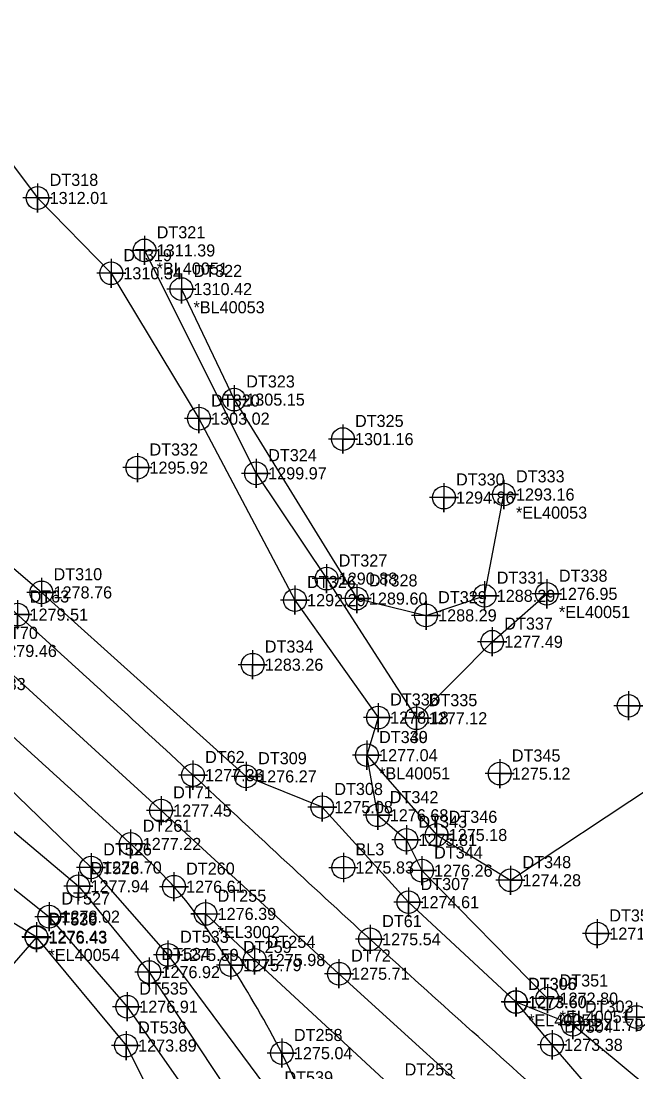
# Model space of a CAD drawing. Extents: x 1391270 to 1392151, y 960049 to 960667.
# Drawn here: x 1391417.5 to 1391544.4, y 960444.8 to 960661.8 of the extents above; entities that cross this region are included whole.
import ezdxf

# ---------------------------------------------------------------- set-up
doc = ezdxf.new("R2010")
doc.units = 0
for name, color, linetype in [('Cogo Default Point CELL', 7, 'Continuous'), ('COGO Default Point Elevation', 7, 'Continuous'), ('COGO Default Point Number', 7, 'Continuous'), ('Exist DTM Breakline', 7, 'Continuous'), ('Exist DTM Breakline Cogo Comment', 7, 'Continuous'), ('Exist DTM Breakline Cogo Elevation', 7, 'Continuous'), ('Exist DTM Breakline Cogo Number', 7, 'Continuous'), ('Exist DTM Breakline Cogo Point CELL', 7, 'Continuous'), ('Exist DTM Crownline', 7, 'Continuous'), ('Exist DTM Crownline Cogo Elevation', 7, 'Continuous'), ('Exist DTM Crownline Cogo Number', 7, 'Continuous'), ('Exist DTM Crownline Cogo Point CELL', 7, 'Continuous'), ('Exist DTM Regular Point CELL', 7, 'Continuous'), ('Exist DTM Regular Point Cogo Elevation', 7, 'Continuous'), ('Exist DTM Regular Point Cogo Number', 7, 'Continuous'), ('Exist Roads EOP', 7, 'Continuous'), ('Exist Roads EOP Cogo Elevation', 7, 'Continuous'), ('Exist Roads EOP Cogo Number', 7, 'Continuous'), ('Exist Roads EOP Cogo Point CELL', 7, 'Continuous'), ('Exist Roads EOT', 7, 'Continuous'), ('Exist Roads EOT Cogo Comment', 7, 'Continuous'), ('Exist Roads EOT Cogo Elevation', 7, 'Continuous'), ('Exist Roads EOT Cogo Number', 7, 'Continuous'), ('Exist Roads EOT Cogo Point CELL', 7, 'Continuous')]:
    doc.layers.add(name, color=color, linetype=linetype)

msp = doc.modelspace()

# ---------------------------------------------------------------- linework, layer by layer
at = {"layer": 'Cogo Default Point CELL'}
for points in [[(1391484.045, 960490.035), (1391484.045, 960487.035)], [(1391481.045, 960487.035), (1391484.045, 960487.035)], [(1391484.045, 960487.035), (1391487.045, 960487.035)], [(1391484.045, 960487.035), (1391484.045, 960484.035)]]:
    msp.add_lwpolyline(points, dxfattribs=at)
msp.add_circle((1391484.045, 960487.035), 2.344, dxfattribs=at)
at = {"layer": 'Exist DTM Breakline'}
for points in [[(1391393.449, 960661.814), (1391420.927, 960625.274), (1391436.139, 960609.727), (1391454.255, 960579.709), (1391474.064, 960542.237), (1391491.205, 960517.974), (1391488.925, 960510.22), (1391503.285, 960493.748), (1391518.522, 960484.392), (1391548.09, 960503.995), (1391563.385, 960512.482)], [(1391443.022, 960614.446), (1391466.033, 960568.417), (1391480.588, 960546.677), (1391499.161, 960517.839), (1391514.762, 960533.642), (1391526.037, 960543.54)], [(1391572.148, 960404.532), (1391566.45, 960414.023), (1391560.493, 960420.45), (1391551.134, 960422.515), (1391527.127, 960450.418), (1391519.65, 960459.266), (1391497.478, 960479.87), (1391479.684, 960499.497), (1391463.962, 960505.846), (1391421.736, 960543.837), (1391384.984, 960575.223), (1391359.376, 960600.331), (1391347.861, 960610.635)], [(1391450.622, 960606.46), (1391461.505, 960583.645), (1391486.818, 960542.56), (1391501.108, 960539.09), (1391513.198, 960543.133), (1391517.176, 960564.054)], [(1391324.233, 960586.705), (1391339.042, 960571.952), (1391361.254, 960553.328), (1391397.359, 960520.55), (1391431.984, 960487.022), (1391447.858, 960468.977), (1391469.387, 960439.951), (1391481.042, 960400.574)], [(1391316.128, 960578.463), (1391335.373, 960567.825), (1391355.688, 960547.259), (1391385.482, 960507.01), (1391423.359, 960476.875), (1391439.432, 960458.285), (1391460.969, 960427.473), (1391472.339, 960397.865), (1391475.509, 960385.212), (1391483.88, 960383.187), (1391486.523, 960363.38), (1391492.773, 960311.276)], [(1391303.798, 960568.714), (1391337.195, 960549.348), (1391355.915, 960524.922), (1391369.834, 960491.808), (1391382.04, 960457.756), (1391381.24, 960442.404), (1391402.896, 960452.148), (1391420.738, 960472.565), (1391439.191, 960450.264), (1391454.114, 960420.78), (1391463.153, 960401.998), (1391468.38, 960380.734), (1391451.764, 960376.78), (1391432.731, 960383.561)], [(1391374.906, 960532.045), (1391391.307, 960515.216), (1391429.365, 960483.152), (1391444, 960465.435), (1391465.005, 960433.545)], [(1391491.131, 960497.813), (1391488.925, 960510.22)], [(1391491.131, 960497.813), (1391497.053, 960492.737), (1391500.273, 960486.377), (1391526.171, 960459.957)], [(1391384.425, 960458.766), (1391387.861, 960492.79), (1391420.701, 960472.719)], [(1391531.404, 960454.553), (1391519.693, 960459.233)], [(1391572.148, 960404.532), (1391576.459, 960415.363), (1391572.673, 960427.425), (1391557.483, 960432.832), (1391531.404, 960454.553)]]:
    msp.add_lwpolyline(points, dxfattribs=at)
at = {"layer": 'Exist DTM Breakline Cogo Point CELL'}
for points in [[(1391420.927, 960628.274), (1391420.927, 960622.274), (1391420.927, 960625.274), (1391423.927, 960625.274), (1391417.927, 960625.274)], [(1391443.022, 960617.446), (1391443.022, 960611.446), (1391443.022, 960614.446), (1391446.022, 960614.446), (1391440.022, 960614.446)], [(1391436.139, 960612.727), (1391436.139, 960606.727), (1391436.139, 960609.727), (1391439.139, 960609.727), (1391433.139, 960609.727)], [(1391450.622, 960609.46), (1391450.622, 960603.46), (1391450.622, 960606.46), (1391453.622, 960606.46), (1391447.622, 960606.46)], [(1391461.505, 960586.645), (1391461.505, 960580.645), (1391461.505, 960583.645), (1391464.505, 960583.645), (1391458.505, 960583.645)], [(1391454.255, 960582.709), (1391454.255, 960576.709), (1391454.255, 960579.709), (1391457.255, 960579.709), (1391451.255, 960579.709)], [(1391466.033, 960571.417), (1391466.033, 960565.417), (1391466.033, 960568.417), (1391469.033, 960568.417), (1391463.033, 960568.417)], [(1391517.176, 960567.054), (1391517.176, 960561.054), (1391517.176, 960564.054), (1391520.176, 960564.054), (1391514.176, 960564.054)], [(1391480.588, 960549.677), (1391480.588, 960543.677), (1391480.588, 960546.677), (1391483.588, 960546.677), (1391477.588, 960546.677)], [(1391421.736, 960546.837), (1391421.736, 960540.837), (1391421.736, 960543.837), (1391424.736, 960543.837), (1391418.736, 960543.837)], [(1391486.818, 960545.56), (1391486.818, 960539.56), (1391486.818, 960542.56), (1391489.818, 960542.56), (1391483.818, 960542.56)], [(1391513.198, 960546.133), (1391513.198, 960540.133), (1391513.198, 960543.133), (1391516.198, 960543.133), (1391510.198, 960543.133)], [(1391526.037, 960546.54), (1391526.037, 960540.54), (1391526.037, 960543.54), (1391529.037, 960543.54), (1391523.037, 960543.54)], [(1391474.064, 960545.237), (1391474.064, 960539.237), (1391474.064, 960542.237), (1391477.064, 960542.237), (1391471.064, 960542.237)], [(1391501.108, 960542.09), (1391501.108, 960536.09), (1391501.108, 960539.09), (1391504.108, 960539.09), (1391498.108, 960539.09)], [(1391514.762, 960536.642), (1391514.762, 960530.642), (1391514.762, 960533.642), (1391517.762, 960533.642), (1391511.762, 960533.642)], [(1391491.205, 960520.974), (1391491.205, 960514.974), (1391491.205, 960517.974), (1391494.205, 960517.974), (1391488.205, 960517.974)], [(1391499.161, 960520.839), (1391499.161, 960514.839), (1391499.161, 960517.839), (1391502.161, 960517.839), (1391496.161, 960517.839)], [(1391488.925, 960513.22), (1391488.925, 960507.22), (1391488.925, 960510.22), (1391491.925, 960510.22), (1391485.925, 960510.22)], [(1391488.926, 960513.219), (1391488.926, 960507.219), (1391488.926, 960510.219), (1391491.926, 960510.219), (1391485.926, 960510.219)], [(1391463.962, 960508.846), (1391463.962, 960502.846), (1391463.962, 960505.846), (1391466.962, 960505.846), (1391460.962, 960505.846)], [(1391479.684, 960502.497), (1391479.684, 960496.497), (1391479.684, 960499.497), (1391482.684, 960499.497), (1391476.684, 960499.497)], [(1391491.131, 960500.813), (1391491.131, 960494.813), (1391491.131, 960497.813), (1391494.131, 960497.813), (1391488.131, 960497.813)], [(1391497.053, 960495.737), (1391497.053, 960489.737), (1391497.053, 960492.737), (1391500.053, 960492.737), (1391494.053, 960492.737)], [(1391503.285, 960496.748), (1391503.285, 960490.748), (1391503.285, 960493.748), (1391506.285, 960493.748), (1391500.285, 960493.748)], [(1391431.984, 960490.022), (1391431.984, 960484.022), (1391431.984, 960487.022), (1391434.984, 960487.022), (1391428.984, 960487.022)], [(1391500.273, 960489.377), (1391500.273, 960483.377), (1391500.273, 960486.377), (1391503.273, 960486.377), (1391497.273, 960486.377)], [(1391518.522, 960487.392), (1391518.522, 960481.392), (1391518.522, 960484.392), (1391521.522, 960484.392), (1391515.522, 960484.392)], [(1391429.365, 960486.152), (1391429.365, 960480.152), (1391429.365, 960483.152), (1391432.365, 960483.152), (1391426.365, 960483.152)], [(1391497.478, 960482.87), (1391497.478, 960476.87), (1391497.478, 960479.87), (1391500.478, 960479.87), (1391494.478, 960479.87)], [(1391423.359, 960479.875), (1391423.359, 960473.875), (1391423.359, 960476.875), (1391426.359, 960476.875), (1391420.359, 960476.875)], [(1391420.701, 960475.719), (1391420.701, 960469.719), (1391420.701, 960472.719), (1391423.701, 960472.719), (1391417.701, 960472.719)], [(1391420.738, 960475.565), (1391420.738, 960469.565), (1391420.738, 960472.565), (1391423.738, 960472.565), (1391417.738, 960472.565)], [(1391447.858, 960471.977), (1391447.858, 960465.977), (1391447.858, 960468.977), (1391450.858, 960468.977), (1391444.858, 960468.977)], [(1391444, 960468.435), (1391444, 960462.435), (1391444, 960465.435), (1391447, 960465.435), (1391441, 960465.435)], [(1391439.432, 960461.285), (1391439.432, 960455.285), (1391439.432, 960458.285), (1391442.432, 960458.285), (1391436.432, 960458.285)], [(1391519.65, 960462.266), (1391519.65, 960456.266), (1391519.65, 960459.266), (1391522.65, 960459.266), (1391516.65, 960459.266)], [(1391519.693, 960462.233), (1391519.693, 960456.233), (1391519.693, 960459.233), (1391522.693, 960459.233), (1391516.693, 960459.233)], [(1391526.171, 960462.957), (1391526.171, 960456.957), (1391526.171, 960459.957), (1391529.171, 960459.957), (1391523.171, 960459.957)], [(1391531.404, 960457.553), (1391531.404, 960451.553), (1391531.404, 960454.553), (1391534.404, 960454.553), (1391528.404, 960454.553)], [(1391439.191, 960453.264), (1391439.191, 960447.264), (1391439.191, 960450.264), (1391442.191, 960450.264), (1391436.191, 960450.264)], [(1391527.127, 960453.418), (1391527.127, 960447.418), (1391527.127, 960450.418), (1391530.127, 960450.418), (1391524.127, 960450.418)]]:
    msp.add_lwpolyline(points, dxfattribs=at)
for centre in [(1391420.927, 960625.274), (1391443.022, 960614.446), (1391436.139, 960609.727), (1391450.622, 960606.46), (1391461.505, 960583.645), (1391454.255, 960579.709), (1391466.033, 960568.417), (1391517.176, 960564.054), (1391480.588, 960546.677), (1391421.736, 960543.837), (1391513.198, 960543.133), (1391526.037, 960543.54), (1391474.064, 960542.237), (1391486.818, 960542.56), (1391501.108, 960539.09), (1391514.762, 960533.642), (1391491.205, 960517.974), (1391499.161, 960517.839), (1391488.925, 960510.22), (1391488.926, 960510.219), (1391463.962, 960505.846), (1391479.684, 960499.497), (1391491.131, 960497.813), (1391503.285, 960493.748), (1391497.053, 960492.737), (1391431.984, 960487.022), (1391500.273, 960486.377), (1391429.365, 960483.152), (1391518.522, 960484.392), (1391497.478, 960479.87), (1391423.359, 960476.875), (1391420.701, 960472.719), (1391420.738, 960472.565), (1391447.858, 960468.977), (1391444, 960465.435), (1391519.65, 960459.266), (1391519.693, 960459.233), (1391526.171, 960459.957), (1391439.432, 960458.285), (1391531.404, 960454.553), (1391439.191, 960450.264), (1391527.127, 960450.418)]:
    msp.add_circle(centre, 2.344, dxfattribs=at)
at = {"layer": 'Exist DTM Crownline'}
msp.add_lwpolyline([(1391336.775, 960598.787), (1391373.255, 960565.397), (1391410.328, 960531.742), (1391446.425, 960498.79), (1391483.147, 960465.095), (1391520.03, 960431.473), (1391553.996, 960400.745), (1391556.572, 960398.448)], dxfattribs=at)
at = {"layer": 'Exist DTM Crownline Cogo Point CELL'}
for points in [[(1391446.425, 960501.79), (1391446.425, 960495.79), (1391446.425, 960498.79), (1391449.425, 960498.79), (1391443.425, 960498.79)], [(1391483.147, 960468.095), (1391483.147, 960462.095), (1391483.147, 960465.095), (1391486.147, 960465.095), (1391480.147, 960465.095)]]:
    msp.add_lwpolyline(points, dxfattribs=at)
for centre in [(1391446.425, 960498.79), (1391483.147, 960465.095)]:
    msp.add_circle(centre, 2.344, dxfattribs=at)
at = {"layer": 'Exist DTM Regular Point CELL'}
for points in [[(1391483.951, 960578.491), (1391483.951, 960572.491), (1391483.951, 960575.491), (1391486.951, 960575.491), (1391480.951, 960575.491)], [(1391441.535, 960572.591), (1391441.535, 960566.591), (1391441.535, 960569.591), (1391444.535, 960569.591), (1391438.535, 960569.591)], [(1391504.801, 960566.408), (1391504.801, 960560.408), (1391504.801, 960563.408), (1391507.801, 960563.408), (1391501.801, 960563.408)], [(1391465.331, 960531.906), (1391465.331, 960525.906), (1391465.331, 960528.906), (1391468.331, 960528.906), (1391462.331, 960528.906)], [(1391542.901, 960523.419), (1391542.901, 960517.419), (1391542.901, 960520.419), (1391545.901, 960520.419), (1391539.901, 960520.419)], [(1391516.32, 960509.41), (1391516.32, 960503.41), (1391516.32, 960506.41), (1391519.32, 960506.41), (1391513.32, 960506.41)], [(1391536.437, 960476.381), (1391536.437, 960470.381), (1391536.437, 960473.381), (1391539.437, 960473.381), (1391533.437, 960473.381)], [(1391544.57, 960459.148), (1391544.57, 960453.148), (1391544.57, 960456.148), (1391547.57, 960456.148), (1391541.57, 960456.148)]]:
    msp.add_lwpolyline(points, dxfattribs=at)
for centre in [(1391483.951, 960575.491), (1391441.535, 960569.591), (1391504.801, 960563.408), (1391465.331, 960528.906), (1391542.901, 960520.419), (1391516.32, 960506.41), (1391536.437, 960473.381), (1391544.57, 960456.148)]:
    msp.add_circle(centre, 2.344, dxfattribs=at)
at = {"layer": 'Exist Roads EOP'}
for points in [[(1391558.507, 960409.653), (1391527.113, 960438.384), (1391489.556, 960472.216), (1391453.007, 960506.097), (1391416.783, 960539.246), (1391379.565, 960572.597), (1391343.959, 960605.485)], [(1391497.16, 960311.857), (1391494.199, 960339.333), (1391490.437, 960370.67), (1391484.795, 960409.189), (1391479.352, 960429.561), (1391471.345, 960448.702), (1391460.843, 960466.873), (1391449.093, 960483.056), (1391440.139, 960491.898), (1391403.899, 960524.912), (1391366.94, 960558.603)]]:
    msp.add_spline(points, degree=3, dxfattribs=at)
at = {"layer": 'Exist Roads EOP Cogo Point CELL'}
for points in [[(1391416.783, 960542.246), (1391416.783, 960536.246), (1391416.783, 960539.246), (1391419.783, 960539.246), (1391413.783, 960539.246)], [(1391453.007, 960509.097), (1391453.007, 960503.097), (1391453.007, 960506.097), (1391456.007, 960506.097), (1391450.007, 960506.097)], [(1391440.139, 960494.898), (1391440.139, 960488.898), (1391440.139, 960491.898), (1391443.139, 960491.898), (1391437.139, 960491.898)], [(1391449.093, 960486.056), (1391449.093, 960480.056), (1391449.093, 960483.056), (1391452.093, 960483.056), (1391446.093, 960483.056)], [(1391489.556, 960475.216), (1391489.556, 960469.216), (1391489.556, 960472.216), (1391492.556, 960472.216), (1391486.556, 960472.216)], [(1391460.843, 960469.873), (1391460.843, 960463.873), (1391460.843, 960466.873), (1391463.843, 960466.873), (1391457.843, 960466.873)], [(1391471.345, 960451.702), (1391471.345, 960445.702), (1391471.345, 960448.702), (1391474.345, 960448.702), (1391468.345, 960448.702)]]:
    msp.add_lwpolyline(points, dxfattribs=at)
for centre in [(1391416.783, 960539.246), (1391453.007, 960506.097), (1391440.139, 960491.898), (1391449.093, 960483.056), (1391489.556, 960472.216), (1391460.843, 960466.873), (1391471.345, 960448.702)]:
    msp.add_circle(centre, 2.344, dxfattribs=at)
at = {"layer": 'Exist Roads EOT'}
msp.add_lwpolyline([(1391542.319, 960398.059), (1391518.576, 960419.517), (1391494.192, 960441.585), (1391465.739, 960467.932), (1391455.599, 960477.451)], dxfattribs=at)
at = {"layer": 'Exist Roads EOT Cogo Point CELL'}
for points in [[(1391455.599, 960480.451), (1391455.599, 960474.451), (1391455.599, 960477.451), (1391452.599, 960477.451), (1391458.599, 960477.451)], [(1391465.739, 960470.932), (1391465.739, 960464.932), (1391465.739, 960467.932), (1391462.739, 960467.932), (1391468.739, 960467.932)]]:
    msp.add_lwpolyline(points, dxfattribs=at)
for centre in [(1391455.599, 960477.451), (1391465.739, 960467.932)]:
    msp.add_circle(centre, 2.344, dxfattribs=at)

# ---------------------------------------------------------------- texts
at = {"layer": 'COGO Default Point Elevation'}
msp.add_text('1275.83', height=2.5, dxfattribs=at).set_placement((1391486.545, 960485.785))
at = {"layer": 'COGO Default Point Number'}
msp.add_text('BL3', height=2.5, dxfattribs=at).set_placement((1391486.545, 960489.535))
at = {"layer": 'Exist DTM Breakline Cogo Comment'}
for s, p in [('*BL40051', (1391445.522, 960609.446)), ('*BL40053', (1391453.122, 960601.46)), ('*EL40053', (1391519.676, 960559.054)), ('*EL40051', (1391528.537, 960538.54)), ('*BL40051', (1391491.426, 960505.219)), ('*EL40054', (1391423.201, 960467.719)), ('*EL40051', (1391522.193, 960454.233)), ('*EL40051', (1391528.671, 960454.957))]:
    msp.add_text(s, height=2.5, dxfattribs=at).set_placement(p)
at = {"layer": 'Exist DTM Breakline Cogo Elevation'}
for s, p in [('1312.01', (1391423.427, 960624.024)), ('1311.39', (1391445.522, 960613.196)), ('1310.34', (1391438.639, 960608.477)), ('1310.42', (1391453.122, 960605.21)), ('1305.15', (1391464.005, 960582.395)), ('1303.02', (1391456.755, 960578.459)), ('1299.97', (1391468.533, 960567.167)), ('1293.16', (1391519.676, 960562.804)), ('1290.88', (1391483.088, 960545.427)), ('1278.76', (1391424.236, 960542.587)), ('1292.29', (1391476.564, 960540.987)), ('1289.60', (1391489.318, 960541.31)), ('1288.29', (1391515.698, 960541.883)), ('1276.95', (1391528.537, 960542.29)), ('1288.29', (1391503.608, 960537.84)), ('1277.49', (1391517.262, 960532.392)), ('1278.18', (1391493.705, 960516.724)), ('1277.12', (1391501.661, 960516.589)), ('1277.04', (1391491.425, 960508.97)), ('1277.04', (1391491.426, 960508.969)), ('1276.27', (1391466.462, 960504.596)), ('1275.08', (1391482.184, 960498.247)), ('1276.68', (1391493.631, 960496.563)), ('1275.81', (1391499.553, 960491.487)), ('1275.18', (1391505.785, 960492.498)), ('1276.70', (1391434.484, 960485.772)), ('1276.26', (1391502.773, 960485.127)), ('1274.28', (1391521.022, 960483.142)), ('1277.94', (1391431.865, 960481.902)), ('1274.61', (1391499.978, 960478.62)), ('1278.02', (1391425.859, 960475.625)), ('1276.43', (1391423.201, 960471.469)), ('1276.43', (1391423.238, 960471.315)), ('1275.59', (1391450.358, 960467.727)), ('1276.92', (1391446.5, 960464.185)), ('1272.80', (1391528.671, 960458.707)), ('1276.91', (1391441.932, 960457.035)), ('1273.60', (1391522.15, 960458.016)), ('1273.60', (1391522.193, 960457.983)), ('1271.79', (1391533.904, 960453.303)), ('1273.89', (1391441.691, 960449.014)), ('1273.38', (1391529.627, 960449.168))]:
    msp.add_text(s, height=2.5, dxfattribs=at).set_placement(p)
at = {"layer": 'Exist DTM Breakline Cogo Number'}
for s, p in [('DT318', (1391423.427, 960627.774)), ('DT321', (1391445.522, 960616.946)), ('DT319', (1391438.639, 960612.227)), ('DT322', (1391453.122, 960608.96)), ('DT323', (1391464.005, 960586.145)), ('DT320', (1391456.755, 960582.209)), ('DT324', (1391468.533, 960570.917)), ('DT333', (1391519.676, 960566.554)), ('DT327', (1391483.088, 960549.177)), ('DT310', (1391424.236, 960546.337)), ('DT331', (1391515.698, 960545.633)), ('DT338', (1391528.537, 960546.04)), ('DT326', (1391476.564, 960544.737)), ('DT328', (1391489.318, 960545.06)), ('DT329', (1391503.608, 960541.59)), ('DT337', (1391517.262, 960536.142)), ('DT336', (1391493.705, 960520.474)), ('DT335', (1391501.661, 960520.339)), ('DT340', (1391491.425, 960512.72)), ('DT339', (1391491.426, 960512.719)), ('DT309', (1391466.462, 960508.346)), ('DT308', (1391482.184, 960501.997)), ('DT342', (1391493.631, 960500.313)), ('DT343', (1391499.553, 960495.237)), ('DT346', (1391505.785, 960496.248)), ('DT526', (1391434.484, 960489.522)), ('DT344', (1391502.773, 960488.877)), ('DT348', (1391521.022, 960486.892)), ('DT528', (1391431.865, 960485.652)), ('DT307', (1391499.978, 960482.37)), ('DT527', (1391425.859, 960479.375)), ('DT529', (1391423.201, 960475.219)), ('DT530', (1391423.238, 960475.065)), ('DT533', (1391450.358, 960471.477)), ('DT534', (1391446.5, 960467.935)), ('DT535', (1391441.932, 960460.785)), ('DT305', (1391522.15, 960461.766)), ('DT306', (1391522.193, 960461.733)), ('DT351', (1391528.671, 960462.457)), ('DT303', (1391533.904, 960457.053)), ('DT536', (1391441.691, 960452.764)), ('DT304', (1391529.627, 960452.918)), ('DT539', (1391471.887, 960442.451))]:
    msp.add_text(s, height=2.5, dxfattribs=at).set_placement(p)
at = {"layer": 'Exist DTM Crownline Cogo Elevation'}
for s, p in [('1279.46', (1391412.828, 960530.492)), ('1277.45', (1391448.925, 960497.54)), ('1275.71', (1391485.647, 960463.845))]:
    msp.add_text(s, height=2.5, dxfattribs=at).set_placement(p)
at = {"layer": 'Exist DTM Crownline Cogo Number'}
for s, p in [('DT70', (1391412.828, 960534.242)), ('DT71', (1391448.925, 960501.29)), ('DT72', (1391485.647, 960467.595))]:
    msp.add_text(s, height=2.5, dxfattribs=at).set_placement(p)
at = {"layer": 'Exist DTM Regular Point Cogo Elevation'}
for s, p in [('1301.16', (1391486.451, 960574.241)), ('1295.92', (1391444.035, 960568.341)), ('1294.86', (1391507.301, 960562.158)), ('1283.26', (1391467.831, 960527.656)), ('1275.12', (1391518.82, 960505.16)), ('1271.84', (1391538.937, 960472.131))]:
    msp.add_text(s, height=2.5, dxfattribs=at).set_placement(p)
at = {"layer": 'Exist DTM Regular Point Cogo Number'}
for s, p in [('DT325', (1391486.451, 960577.991)), ('DT332', (1391444.035, 960572.091)), ('DT330', (1391507.301, 960565.908)), ('DT334', (1391467.831, 960531.406)), ('DT345', (1391518.82, 960508.91)), ('DT352', (1391538.937, 960475.881))]:
    msp.add_text(s, height=2.5, dxfattribs=at).set_placement(p)
at = {"layer": 'Exist Roads EOP Cogo Elevation'}
for s, p in [('1279.51', (1391419.283, 960537.996)), ('1279.33', (1391406.399, 960523.662)), ('1277.36', (1391455.507, 960504.847)), ('1277.22', (1391442.639, 960490.648)), ('1276.61', (1391451.593, 960481.806)), ('1275.54', (1391492.056, 960470.966)), ('1275.79', (1391463.343, 960465.623)), ('1275.04', (1391473.845, 960447.452))]:
    msp.add_text(s, height=2.5, dxfattribs=at).set_placement(p)
at = {"layer": 'Exist Roads EOP Cogo Number'}
for s, p in [('DT63', (1391419.283, 960541.746)), ('DT62', (1391455.507, 960508.597)), ('DT261', (1391442.639, 960494.398)), ('DT260', (1391451.593, 960485.556)), ('DT61', (1391492.056, 960474.716)), ('DT259', (1391463.343, 960469.373)), ('DT258', (1391473.845, 960451.202))]:
    msp.add_text(s, height=2.5, dxfattribs=at).set_placement(p)
at = {"layer": 'Exist Roads EOT Cogo Comment'}
msp.add_text('*EL3002', height=2.5, dxfattribs=at).set_placement((1391458.099, 960472.451))
at = {"layer": 'Exist Roads EOT Cogo Elevation'}
for s, p in [('1276.39', (1391458.099, 960476.201)), ('1275.98', (1391468.239, 960466.682))]:
    msp.add_text(s, height=2.5, dxfattribs=at).set_placement(p)
at = {"layer": 'Exist Roads EOT Cogo Number'}
for s, p in [('DT255', (1391458.099, 960479.951)), ('DT254', (1391468.239, 960470.432)), ('DT253', (1391496.692, 960444.085))]:
    msp.add_text(s, height=2.5, dxfattribs=at).set_placement(p)

doc.saveas('drawing.dxf')
